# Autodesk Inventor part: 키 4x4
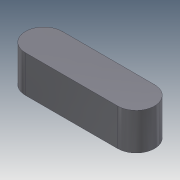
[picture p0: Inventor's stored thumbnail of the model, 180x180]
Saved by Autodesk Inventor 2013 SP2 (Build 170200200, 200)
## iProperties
Company: 한국ATC센터
Created: 2014-10
Part Number: 키 4x4
Document SubType Name: Modeling
Designer: KYOUNG IL JANG
Density: 1 g/cm^3
Mass: 0.210265 g
Surface Area: 2.35398 cm^2
Volume: 0.210265 cm^3
Material: 일반
Author: KYOUNG IL JANG
Revision Number: 1
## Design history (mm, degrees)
sketch "스케치1"
  geometry: L1 (-5, -2)-(5, -2); L2 (5, 2)-(-5, 2); A1 r 2 centre (5, 0) between (5, -2) and (5, 2); A2 r 2 centre (-5, 0) between (-5, 2) and (-5, -2); 2 further points
  constraints: 4 end point, 4 point on circle, 4 tangent, 2 centre point, 1 horizontal, 1 horizontal alignment, 1 midpoint, 1 parallel, 1 vertical alignment
  dimensions: "d0" = 4 distance between parallel lines of L1 L2; "d1" = 14 dimension on A1 A2
extrude "돌출1" new body sketch "스케치1" stored distance "d2" = 4; taper "d3" = 0 deg
node "솔리드1"
